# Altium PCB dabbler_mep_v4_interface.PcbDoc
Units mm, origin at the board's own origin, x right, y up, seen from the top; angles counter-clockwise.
Board outline 33.45 x 16.5 mm, 2 copper layers (Top Layer, Bottom Layer); 2 components, 5 nets, 12 pads, 0 vias.
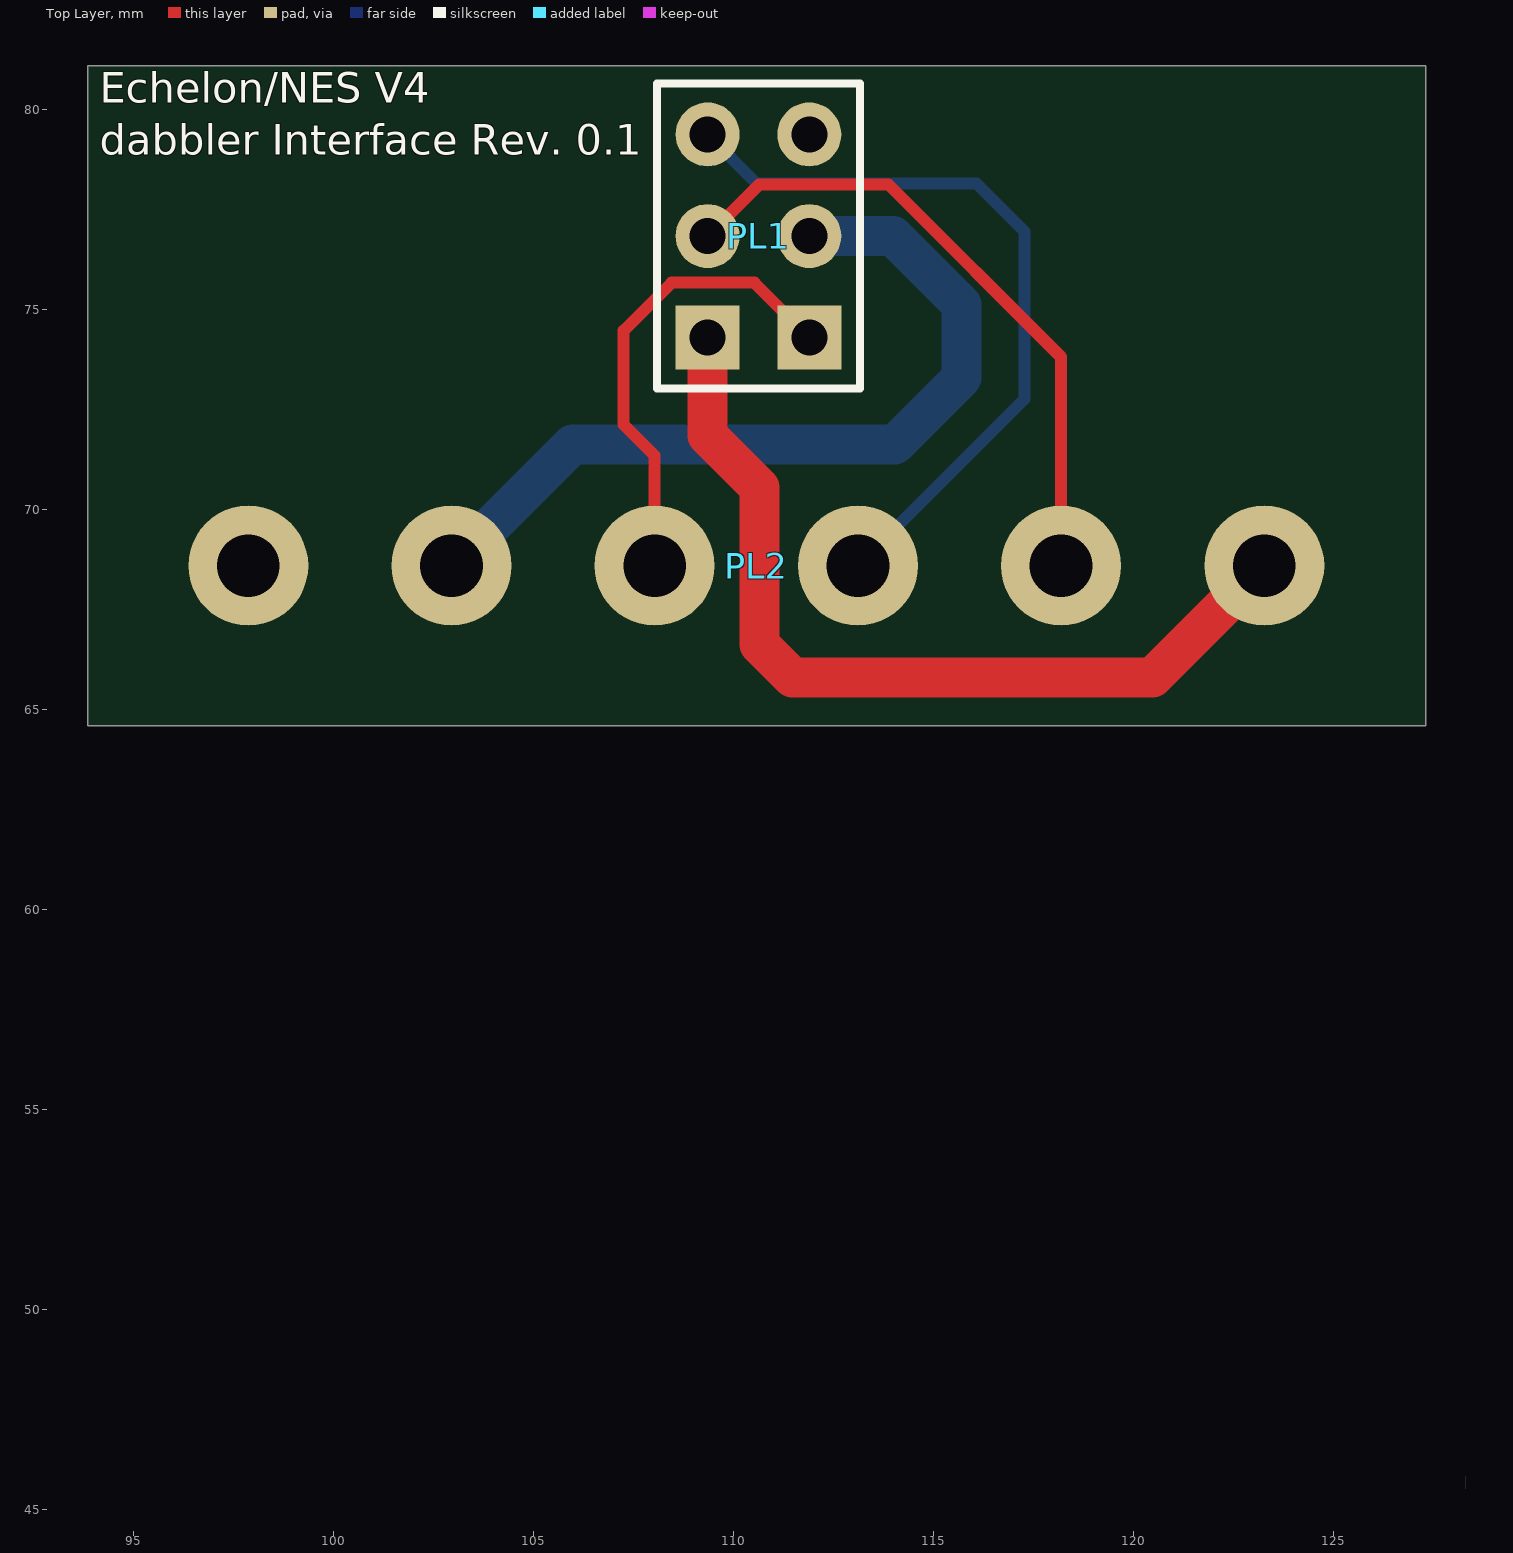
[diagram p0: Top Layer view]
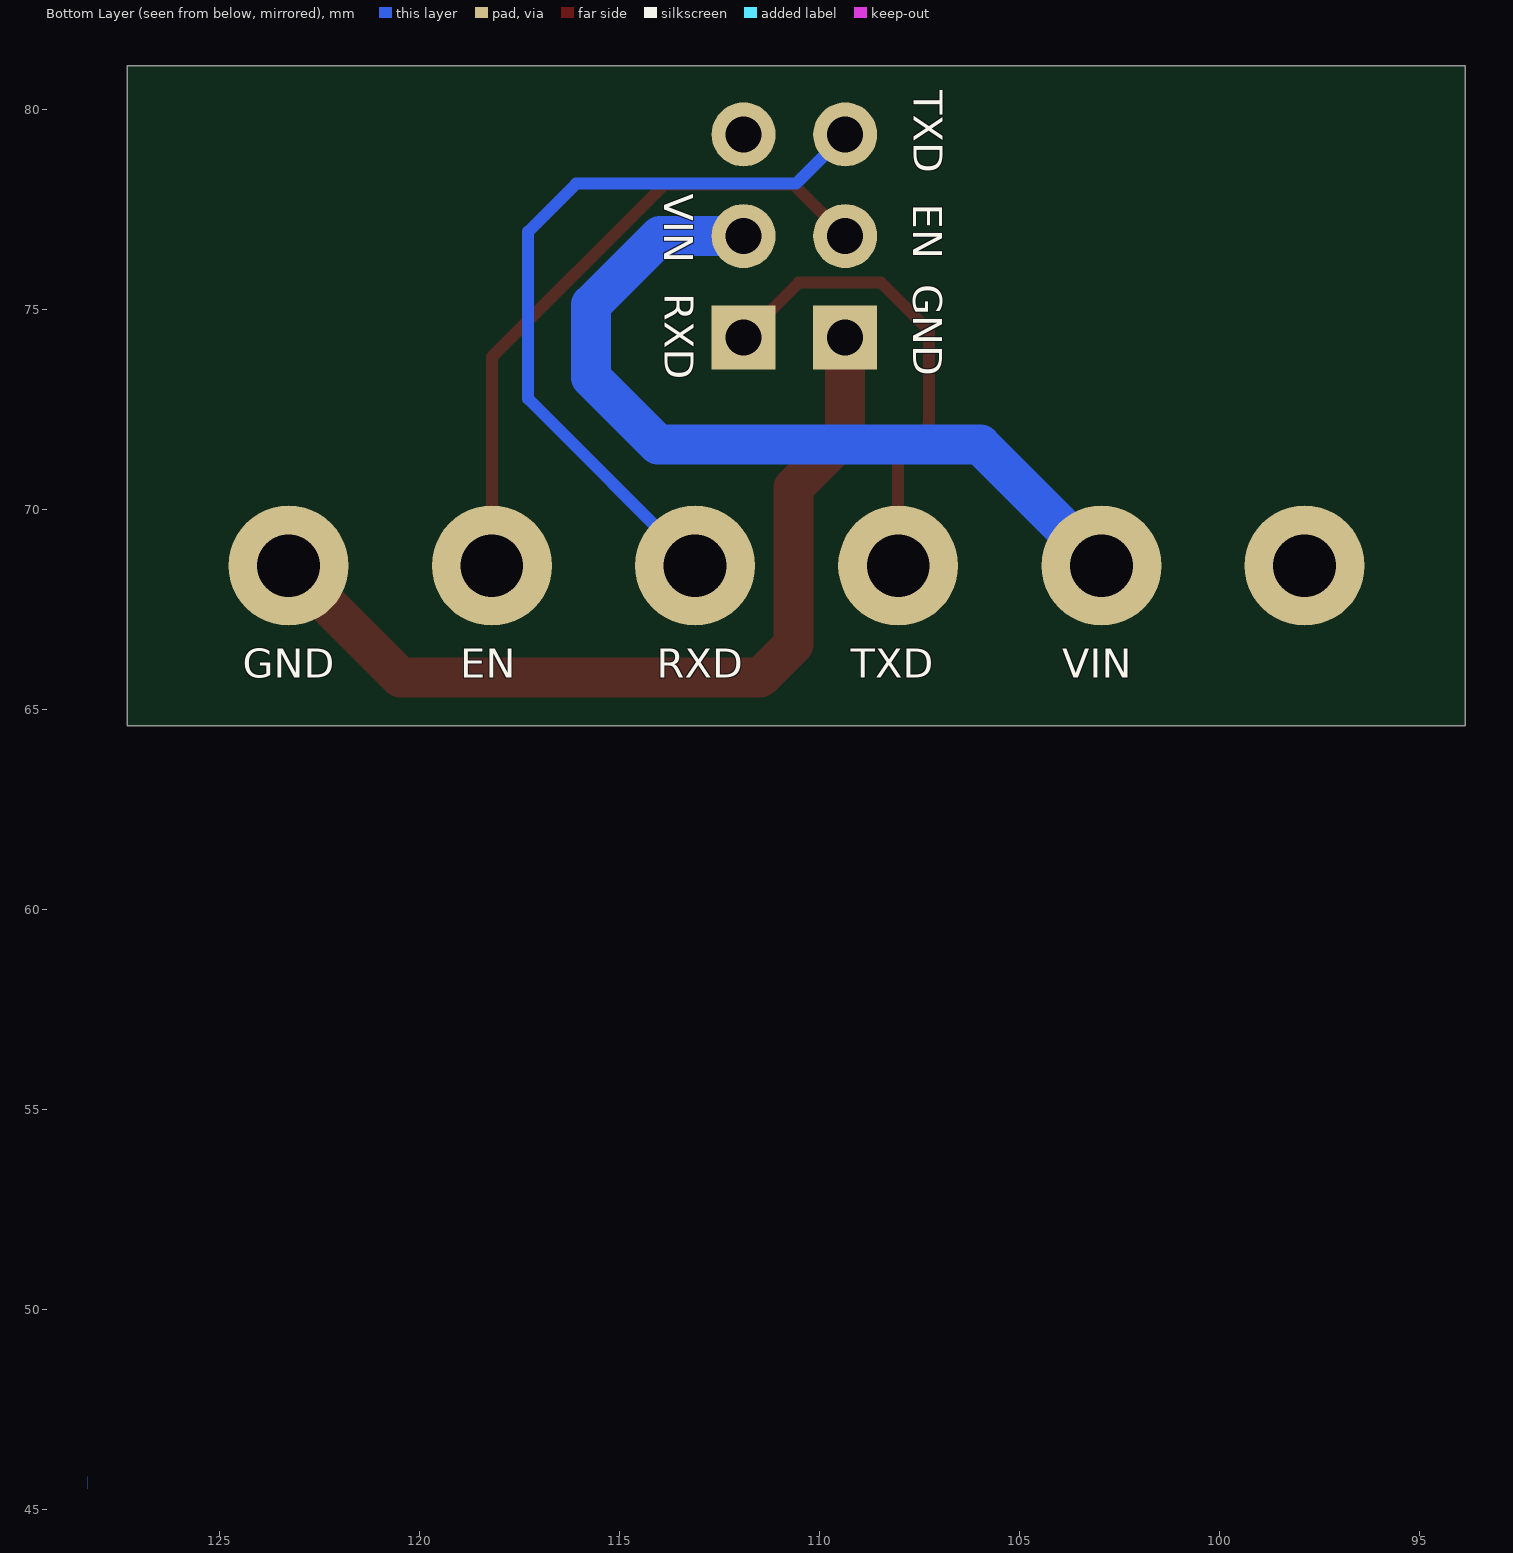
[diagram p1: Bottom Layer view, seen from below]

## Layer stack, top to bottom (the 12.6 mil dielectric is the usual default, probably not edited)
Top Solder: solder mask 0.0102, Solder Resist, Dk 3.5
Top Layer: signal copper 0.0356
Dielectric 1: dielectric 0.32, FR-4, Dk 4.8
Bottom Layer: signal copper 0.0356
Bottom Solder: solder mask 0.0102, Solder Resist, Dk 3.5

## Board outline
93.85,64.6 127.3,64.6 127.3,81.1 93.85,81.1

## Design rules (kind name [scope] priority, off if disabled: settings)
Clearance [All] p1: gap=0.254 ignorepadtopadclearanceinfootprint=FALSE except(0: Arc-Hole Track-Hole SMDPad-Hole THPad-Hole Via-Hole Fill-Hole Poly-Hole Region-Hole Text-Hole; 0.2: Arc-SMDPad Arc-THPad Track-SMDPad Track-THPad SMDPad-SMDPad SMDPad-THPad)
PlaneConnect [All] p1: planeconnectstyle=Relief reliefexpansion=0.508 reliefentries=4 reliefconductorwidth=0.5 reliefairgap=0.254
PolygonConnect PolygonConnect_2 [IsVia] p1: connectstyle=Direct reliefconductorwidth=0.254 reliefentries=4 polygonreliefangle="90 Angle" airgapwidth=0.254
PolygonConnect PolygonConnect_1 [(InNet('VBUS') OR InNet('NetF1_2'))] p2: connectstyle=Direct reliefconductorwidth=0.254 reliefentries=4 polygonreliefangle="90 Angle" airgapwidth=0.254
PolygonConnect [All] p3: connectstyle=Relief reliefconductorwidth=0.5 reliefentries=4 polygonreliefangle="90 Angle" airgapwidth=0.254
RoutingVias [All] p1: holewidth=0.711 width=1.27 viastyle="Through Hole" minholewidth=0.711 minwidth=1.27 maxholewidth=0.711 maxwidth=1.27
SolderMaskExpansion [All] p1: expansion=0.102 istentingtop=FALSE
Width [All] p1: maxlimit=1 minlimit=0.2 preferedwidth=0.25 minimp=50.000000 maximp=50.000000 favimp=50.000000
29 further rules are at their usual default settings.

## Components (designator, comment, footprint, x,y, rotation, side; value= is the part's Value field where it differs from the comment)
PL1 "2x3-pin Male Header 2.54mm straight" "2x3-pin 2.54mm header" 110.62,76.84 r90 top locked
PL2 "6-pin male 5.08mm" "6-pin male 5.08mm-Footprint-1" 123.265,68.6 r180 top

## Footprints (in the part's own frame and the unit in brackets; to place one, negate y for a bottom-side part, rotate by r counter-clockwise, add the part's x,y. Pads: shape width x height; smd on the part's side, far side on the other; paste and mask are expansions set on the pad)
"2x3-pin 2.54mm header" [mm]
  rect 1.6x1.6 hole 0.9: 1(-2.54,1.27) 2(-2.54,-1.27)
  round 1.6 hole 0.9: 3(0,1.27) 4(0,-1.27) 5(2.54,1.27) 6(2.54,-1.27)
  silkscreen extent -3.81,-2.54 3.81,2.54, body extent -3.81,-2.54 3.81,2.54, height 9.5
"6-pin male 5.08mm-Footprint-1" [mm]
  round 3 hole 1.57: 1(0,0) 2(5.08,0) 3(10.16,0) 4(15.24,0) 5(20.32,0) 6(25.4,0)

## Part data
PL1: library part CMP-003-0019-0.0
PL2: library part CMP-003-0039-0.0, "KK® Header, Vertical, Round Pin, 6 Circuits, Tin (Sn) Plating, Pin Length 19.05mm", Contact Resistance=10mR, Current Rating=7A, Flammability Rating="UL94 V-2", Insulation Resistance=500GR, Max Operating Temperature=75°C, Min Operating Temperature=0°C, Package Quantity=2000, Voltage Rating=250V

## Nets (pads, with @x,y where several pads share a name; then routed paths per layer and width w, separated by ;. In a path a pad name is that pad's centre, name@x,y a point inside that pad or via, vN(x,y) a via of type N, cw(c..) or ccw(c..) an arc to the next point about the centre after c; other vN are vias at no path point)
ENABLE: PL1.3 PL2.2 | length 16.4
  Top Layer w0.3: PL1.3 110.635,78.125 113.875,78.125 118.185,73.815 PL2.2
GND: PL1.1 PL2.1 | length 22.3
  Top Layer w1: PL1.1 109.35,71.85 110.64,70.56 110.64,66.635 111.475,65.8 120.465,65.8 PL2.1
RXD: PL1.2 PL2.4 | length 11.9
  Top Layer w0.3: PL2.4 108.025,71.35 107.25,72.125 107.25,74.475 108.45,75.675 110.515,75.675 PL1.2
TXD: PL1.5 PL2.3 | length 19
  Bottom Layer w0.3: PL1.5 110.58,78.15 116.075,78.15 117.275,76.95 117.275,72.77 PL2.3
VCC: PL1.4 PL2.5 | length 21
  Bottom Layer w1: PL2.5 105.97,71.625 114.025,71.625 115.7,73.3 115.7,75.125 113.985,76.84 PL1.4
pads on no net: PL1.6 PL2.6

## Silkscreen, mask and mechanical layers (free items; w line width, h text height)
Top Overlay:
  text "Echelon/NES V4  / dabbler Interface Rev. 0.1" at 94.15,78.625 h1.3
Bottom Overlay:
  text "TXD" at 107.89,80.49 h1.25 r90
  text "VIN" at 114.125,77.9 h1.25 r90
  text "EN" at 107.9,77.65 h1.25 r90
  text "GND" at 107.895,75.64 h1.25 r90
  text "RXD" at 114.115,75.415 h1.25 r90
  text "VIN" at 103.925,65.55 h1.25
  text "TXD" at 109.215,65.549 h1.25
  text "RXD" at 114.065,65.549 h1.25
  text "EN" at 118.975,65.55 h1.25
  text "GND" at 124.415,65.55 h1.25
Outline:
  lines w0.1: 93.85,64.6 93.85,81.1 ; 93.85,64.6 124.23,64.6 ; 93.85,64.6 124.23,64.6 ; 93.85,64.6 93.85,81.1 ; 93.85,81.1 110.365,81.1 ; 93.85,81.1 110.365,81.1 ; 110.365,81.1 127.3,81.1 ; 110.365,81.1 127.3,81.1 ; 124.23,64.6 127.3,64.6 ; 124.23,64.6 127.3,64.6 ; 127.3,64.6 127.3,81.1 ; 127.3,64.6 127.3,81.1 ; 101.575,75.775 101.575,75.775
